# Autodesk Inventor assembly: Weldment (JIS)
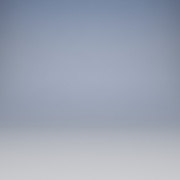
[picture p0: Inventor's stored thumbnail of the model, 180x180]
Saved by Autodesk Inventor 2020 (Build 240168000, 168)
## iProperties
Length Units: 11269
Angle Units: 11283
Time Units: 11279
Mass Units: 11290
Length Display Precision: 3
Angle Display Precision: 2
Part Number: Weldment (JIS)
Document SubType Name: Weldment
Created: 2002-06
Designer: smithga
Created: 2002-08
Designer: F.Stasiak
Weld Material: Welded Aluminum-6061
Catalog Web Link: www.expertbooks.pl
Manager: www.cadconsulting.pl
Company: Fabian Stasiak CAD Consulting
Control State: 0
Master: False
Shininess: 64.0
Angle Units: 11279
Time Units: 11290
Mass Units: 11283
Compacted: True
Density: 0.0
Volumn: 0.0
Area: 0.0
PropertySet Name: Model Information
Author: F.Stasiak
Subject: Zbiór ćwiczeń. Autodesk Inventor 2020. Kurs Professional
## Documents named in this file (1)
- M:\AUTOBUILD\M24_168_RTM\Application\App\Templates\en-US\Metric\Weldment (JIS).iam
